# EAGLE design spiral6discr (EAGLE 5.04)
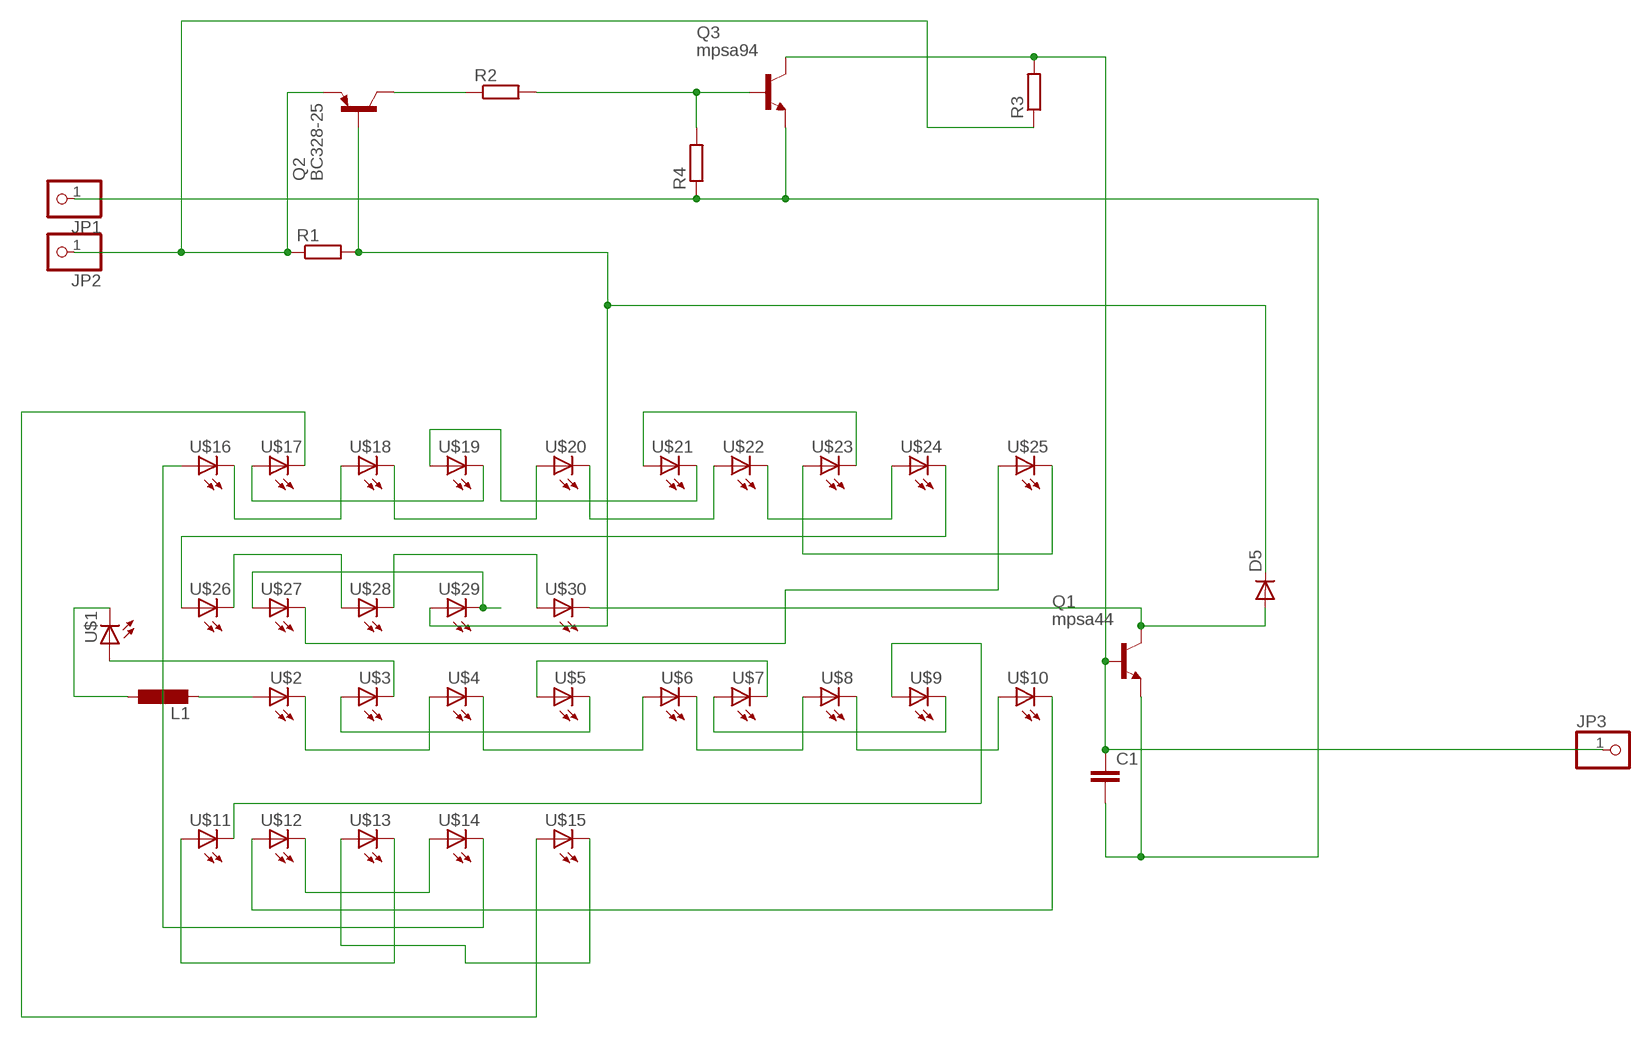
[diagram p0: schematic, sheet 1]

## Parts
C1  C-EU025-024X044  [C025-024X044]
D5  DIODE-D-2.5  [D-2.5]
JP1  PINHD-1X1  [1X01]
JP2  PINHD-1X1  [1X01]
JP3  PINHD-1X1  [1X01]
L1  L-EU0207/10  [0207/10]
Q1  mpsa44  BC338-40  [TO92-EBC]
Q2  BC328-25  [TO92-EBC]
Q3  mpsa94  BC338-40  [TO92-EBC]
R1  R-EU_0207/7  [0207/7]
R2  R-EU_0207/7  [0207/7]
R3  R-EU_0207/7  [0207/7]
R4  R-EU_0207/7  [0207/7]
U$1  LED5MM  [LED5MM]
U$2  LED5MM  [LED5MM]
U$3  LED5MM  [LED5MM]
U$4  LED5MM  [LED5MM]
U$5  LED5MM  [LED5MM]
U$6  LED5MM  [LED5MM]
U$7  LED5MM  [LED5MM]
U$8  LED5MM  [LED5MM]
U$9  LED5MM  [LED5MM]
U$10  LED5MM  [LED5MM]
U$11  LED5MM  [LED5MM]
U$12  LED5MM  [LED5MM]
U$13  LED5MM  [LED5MM]
U$14  LED5MM  [LED5MM]
U$15  LED5MM  [LED5MM]
U$16  LED5MM  [LED5MM]
U$17  LED5MM  [LED5MM]
U$18  LED5MM  [LED5MM]
U$19  LED5MM  [LED5MM]
U$20  LED5MM  [LED5MM]
U$21  LED5MM  [LED5MM]
U$22  LED5MM  [LED5MM]
U$23  LED5MM  [LED5MM]
U$24  LED5MM  [LED5MM]
U$25  LED5MM  [LED5MM]
U$26  LED5MM  [LED5MM]
U$27  LED5MM  [LED5MM]
U$28  LED5MM  [LED5MM]
U$29  LED5MM  [LED5MM]
U$30  LED5MM  [LED5MM]

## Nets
N$1: C1.2 JP1.1 Q1.E Q3.E R4.1
N$2: U$2.K(C) U$4.A
N$3: U$4.K(C) U$6.A
N$4: U$6.K(C) U$8.A
N$5: U$8.K(C) U$10.A
N$6: U$1.A U$3.K(C)
N$7: U$3.A U$5.K(C)
N$8: U$5.A U$7.K(C)
N$9: U$7.A U$9.K(C)
N$10: U$10.K(C) U$12.A
N$11: U$12.K(C) U$14.A
N$12: U$14.K(C) U$16.A
N$13: U$16.K(C) U$18.A
N$14: U$18.K(C) U$20.A
N$15: U$20.K(C) U$22.A
N$16: U$22.K(C) U$24.A
N$17: U$24.K(C) U$26.A
N$18: U$26.K(C) U$28.A
N$19: U$28.K(C) U$30.A
N$20: JP2.1 Q2.E R1.1 R3.1
N$21: L1.2 U$2.A
N$22: L1.1 U$1.K(C)
N$23: U$27.A U$29.K(C)
N$24: U$25.A U$27.K(C)
N$26: Q2.C R2.1
N$27: U$9.A U$11.K(C)
N$28: Q3.B R2.2 R4.2
N$29: U$11.A U$13.K(C)
N$30: U$13.A U$15.K(C)
N$31: U$15.A U$17.K(C)
N$32: U$17.A U$19.K(C)
N$33: U$19.A U$21.K(C)
N$34: U$21.A U$23.K(C)
N$35: U$23.A U$25.K(C)
N$36: D5.A Q1.C U$30.K(C)
N$37: C1.1 JP3.1 Q1.B Q3.C R3.2
V300: D5.C Q2.B R1.2 U$29.A

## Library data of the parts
C1 = rcl-2:C-EU: CAPACITOR, European symbol
D5 = diode-1:DIODE-: DIODE
JP1-JP3 = pinhead:PINHD-1X1: PIN HEADER
L1 = rcl-2:L-EU: INDUCTOR, European symbol
Q1 Q3 = transistor-npn:BC338*: NPN Transistor
Q2 = transistor-pnp:BC328*: PNP Transistror
R1-R4 = rcl-2:R-EU_: RESISTOR, European symbol
U$1-U$30 = led(2):LED: LED

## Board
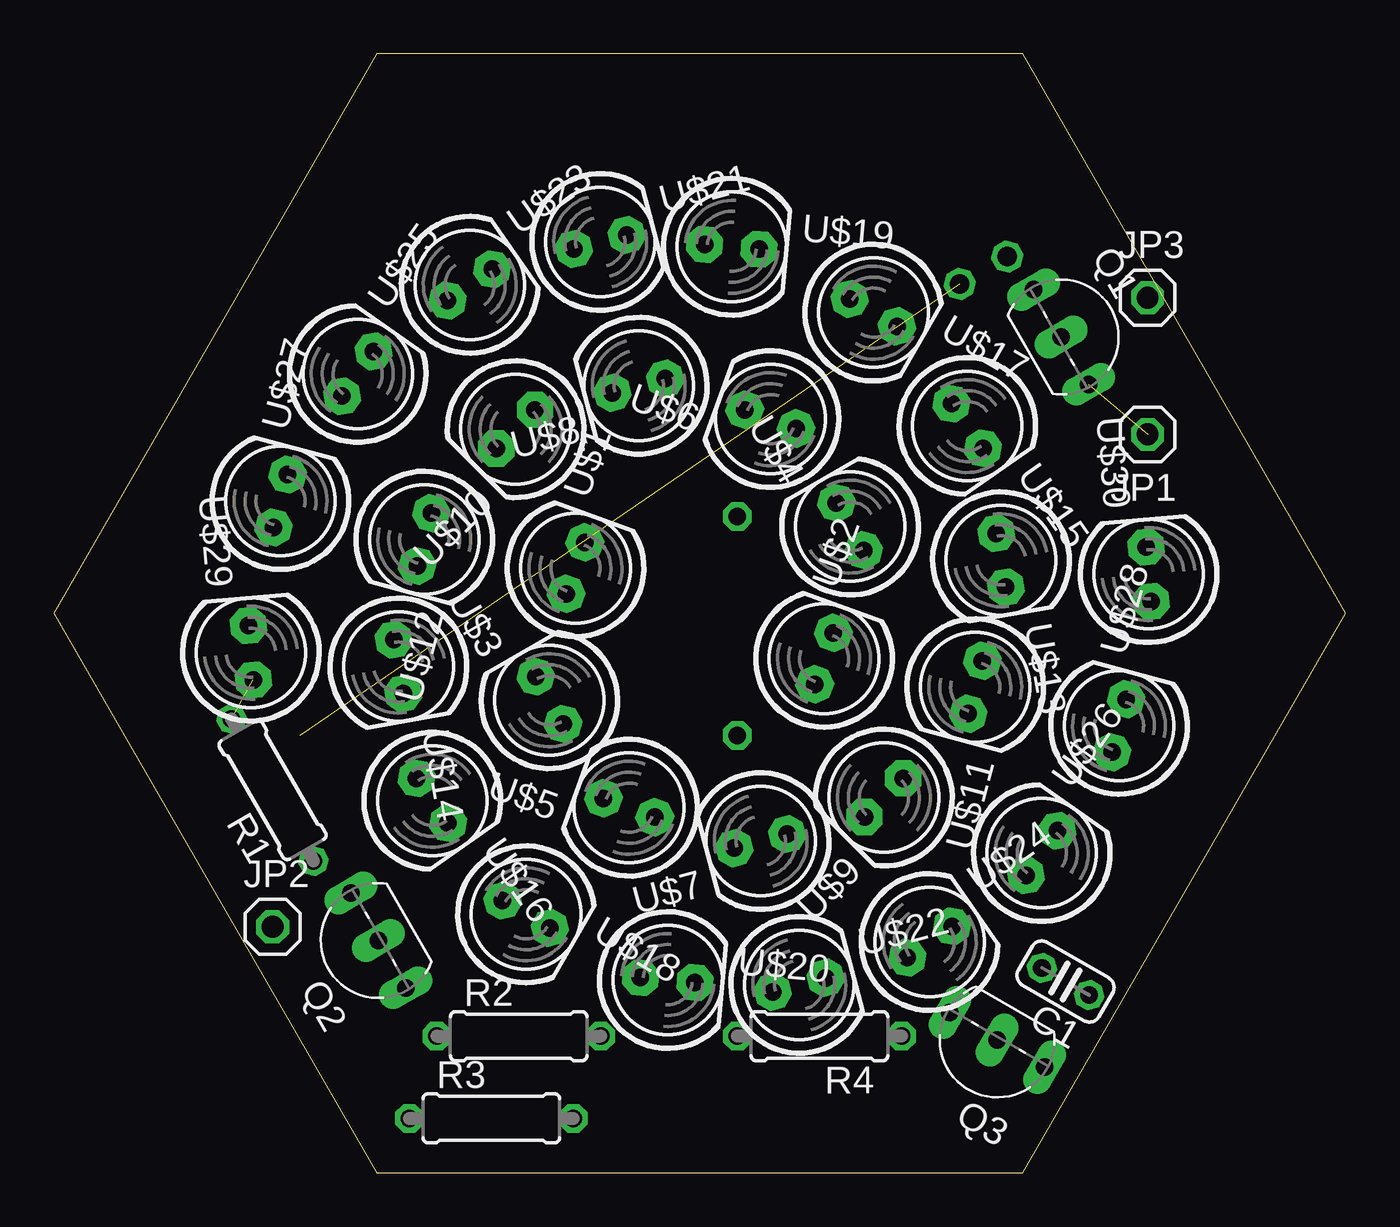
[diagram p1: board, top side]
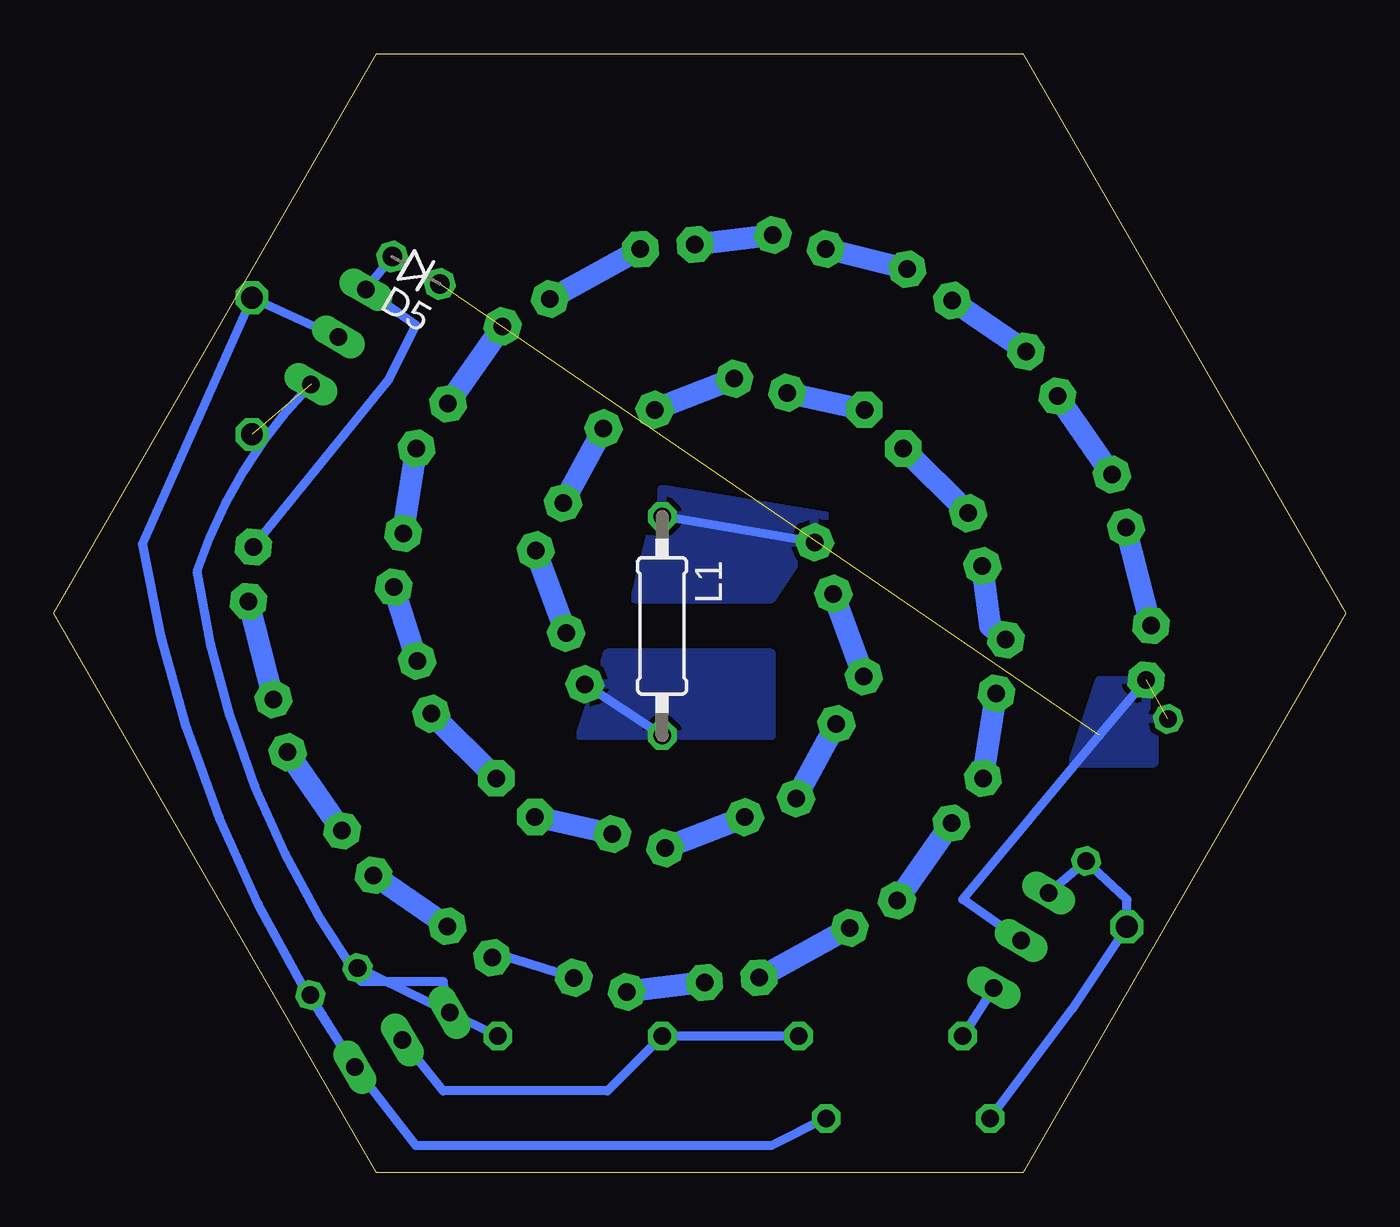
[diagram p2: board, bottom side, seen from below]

Size 60 x 51.96 mm. Coordinates in mm from the lower left corner, seen from the top.
Outline: 15,0 45,0 60,25.98 45,51.96 15,51.96 0,25.98 15,0
Copper layers (1*16): Top 0.035mm / dielectric 1.5mm / Bottom 0.035mm
Design rules "default": minimum track width 10mil, minimum drill 24mil, track to track 8mil, track to pad 8mil, pad to pad 8mil, via to via 8mil, smd to smd 8mil, copper to edge 40mil, drill to drill 8mil, minimum pad ring 10mil, minimum via ring 8mil, stop-mask expansion 4mil, vias tented up to drill 0mil, thermal gap 10mil

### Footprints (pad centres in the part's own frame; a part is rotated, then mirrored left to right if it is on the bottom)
C025-024X044 = drill 0.813 octagon: 1 -1.27,0; 2 1.27,0
D-2.5 = drill 0.9 octagon: A 1.27,0; C -1.27,0
1X01 = drill 1.016 octagon: 1 0,0
0207/10 = drill 0.813 octagon: 1 -5.08,0; 2 5.08,0
TO92-EBC = drill 0.813 long: B 0,-1.27; C -2.54,-1.27; E 2.54,-1.27
0207/7 = drill 0.813 octagon: 1 -3.81,0; 2 3.81,0
LED5MM = drill 0.813 pad 1.676 octagon: A -1.27,0; K 1.27,0

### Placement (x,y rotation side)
C1  46.99,8.89 150 top
D5  43.18,41.91 150 bottom
JP1  50.8,34.29 180 top
JP2  10.16,11.43 0 top
JP3  50.8,40.64 0 top
L1  31.75,25.4 270 bottom
Q1  47.88,39.45 300 top
Q2  13.97,10.16 120 top
Q3  43.18,5.08 150 top
R1  10.16,17.78 120 top
R2  21.59,6.35 0 top
R3  20.32,2.54 0 top
R4  35.56,6.35 180 top
U$1  24.23,28.08 70 top
U$2  35.77,23.88 70 top
U$3  23.02,21.95 120 top
U$4  36.98,30.01 120 top
U$5  26.72,16.96 160 top
U$6  33.28,35 160 top
U$7  32.83,15.41 195 top
U$8  27.17,36.55 195 top
U$9  38.55,17.43 225 top
U$10  21.45,34.53 225 top
U$11  42.8,22.55 255 top
U$12  17.2,29.41 255 top
U$13  43.99,28.45 280 top
U$14  16.01,23.51 280 top
U$15  42.42,34.68 305 top
U$16  17.58,17.28 305 top
U$17  38.06,39.95 330 top
U$18  21.94,12.01 330 top
U$19  31.49,43 355 top
U$20  28.51,8.96 355 top
U$21  25.38,43.23 14.9 top
U$22  34.62,8.73 14.9 top
U$23  19.32,41.23 35 top
U$24  40.68,10.73 35 top
U$25  14.12,37.1 54.9 top
U$26  45.88,14.86 54.9 top
U$27  10.53,31.2 75 top
U$28  49.47,20.76 75 top
U$29  9.15,24.16 95 top
U$30  50.85,27.8 95 top

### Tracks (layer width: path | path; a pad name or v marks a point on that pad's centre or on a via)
N$1  (1 unrouted)
  Bottom 0.406: Q3.E 41.91,8.89 45.72,8.89 arc27 53.34,27.94 arc26 Q1.E | Q3.E C1.2 | R4.1 Q3.E
N$2
  Bottom 1.016: U$2.K U$4.A
N$3
  Bottom 1.016: U$6.A U$4.K
N$4
  Bottom 1.016: U$8.A U$6.K
N$5
  Bottom 1.016: U$10.A U$8.K
N$6
  Bottom 1.016: U$3.K U$1.A
N$7
  Bottom 1.016: U$5.K U$3.A
N$8
  Bottom 1.016: U$5.A U$7.K
N$9
  Bottom 1.016: U$7.A U$9.K
N$10
  Bottom 1.016: U$12.A U$10.K
N$11
  Bottom 1.016: U$12.K 16.51,25.4 U$14.A
N$12
  Bottom 1.016: U$16.A U$14.K
N$13
  Bottom 1.016: U$18.A U$16.K
N$14
  Bottom 1.016: U$20.A U$18.K
N$15
  Bottom 1.016: U$20.K U$22.A
N$16
  Bottom 0.406: U$22.K 39.37,10.16 U$24.A
N$17
  Bottom 1.016: U$24.K U$26.A
N$18
  Bottom 1.016: U$26.K U$28.A
N$19
  Bottom 1.016: U$28.K U$30.A
N$20
  Bottom 0.406: R3.1 12.7,7.62 JP2.1 10.16,12.7 R1.1 Q2.E
N$21
  Bottom 0.406: L1.2 U$2.A
  pour Bottom: 34.29,24.13 35.56,20.32 26.67,20.32 26.67,24.13
N$22
  Bottom 0.406: U$1.K L1.1
  pour Bottom: 24.13,30.48 31.75,31.75 33.02,26.67 26.67,26.67
N$23
  Bottom 1.016: U$29.K U$27.A
N$24
  Bottom 1.016: U$27.K U$25.A
N$26
  Bottom 0.406: R2.1 Q2.C
N$27
  Bottom 1.016: U$9.A U$11.K
N$28
  Bottom 0.406: Q3.B 41.91,3.81 34.29,3.81 R4.2 R2.2
N$29
  Bottom 1.016: U$11.A U$13.K
N$30
  Bottom 1.016: U$13.A U$15.K
N$31
  Bottom 1.016: U$15.A U$17.K
N$32
  Bottom 1.016: U$19.K 36.83,40.64 U$17.A
N$33
  Bottom 1.016: U$19.A U$21.K
N$34
  Bottom 1.016: U$23.K U$21.A
N$35
  Bottom 1.016: U$25.K U$23.A
N$36
  Bottom 0.406: U$30.K 44.45,36.83 43.18,39.37 Q1.C D5.A
N$37
  Bottom 0.406: Q3.C arc26 55.88,29.21 JP3.1 Q1.B | R3.2 26.67,1.27 43.18,1.27 Q3.C | Q3.C C1.1
V300  (2 unrouted)
  Bottom 0.406: Q2.B 17.78,12.7 11.43,20.32 U$29.A
  pour Bottom: 8.89,22.86 11.43,22.86 12.7,19.05 8.89,19.05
